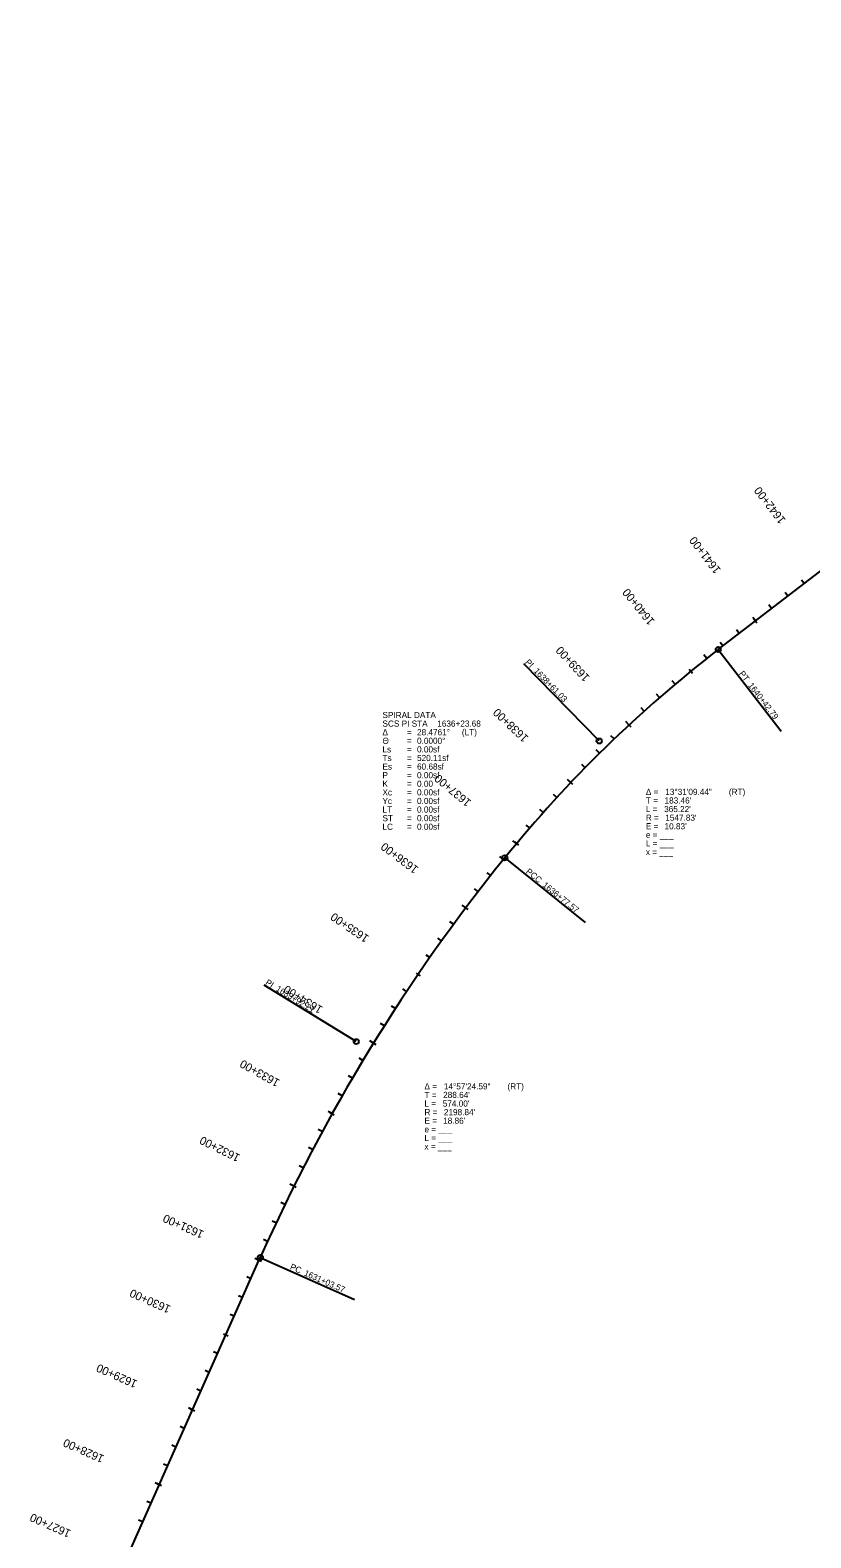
# Model space of a CAD drawing. Extents: x 14119411 to 14122090, y 8669365 to 8673150.
# Drawn here: x 14120185 to 14121138, y 8671257 to 8673099 of the extents above; entities that cross this region are included whole.
import ezdxf

# ---------------------------------------------------------------- set-up
doc = ezdxf.new("R2010")
doc.units = 0
for name, color, linetype in [('Alignment', 7, 'Continuous'), ('Default', 7, 'Continuous'), ('TextAlignment', 7, 'Continuous'), ('TextAlignmentLrg', 7, 'Continuous'), ('TextAlignmentSml', 7, 'Continuous')]:
    doc.layers.add(name, color=color, linetype=linetype)

msp = doc.modelspace()

# ---------------------------------------------------------------- linework, layer by layer
at = {"layer": 'Alignment'}
for p, q in [((14121025, 8672342.6), (14122009.4, 8673099.3)), ((14120263.5, 8671145.2), (14120465.7, 8671599.8))]:
    msp.add_line(p, q, dxfattribs=at)
for centre, radius, start, end in [((14121968.4, 8671115.4), 1547.8, 127.5512, 141.0704), ((14122474.8, 8670706.4), 2198.8, 141.0704, 156.0273)]:
    msp.add_arc(centre, radius, start, end, dxfattribs=at)
at = {"layer": 'Default'}
for p, q in [((14121025, 8672342.6), (14122009.4, 8673099.3)), ((14120263.5, 8671145.2), (14120465.7, 8671599.8))]:
    msp.add_line(p, q, dxfattribs=at)
for centre, radius, start, end in [((14121968.4, 8671115.4), 1547.8, 127.5512, 141.0704), ((14122474.8, 8670706.4), 2198.8, 141.0704, 156.0273)]:
    msp.add_arc(centre, radius, start, end, dxfattribs=at)
at = {"layer": 'TextAlignment'}
for p, q in [((14121025, 8672342.6), (14121101.8, 8672242.7)), ((14120879.6, 8672230.8), (14120787.4, 8672325.2)), ((14120787.4, 8672325.2), (14120787.4, 8672325.2)), ((14121101.8, 8672242.7), (14121101.8, 8672242.7)), ((14120764.3, 8672088), (14120862.3, 8672008.9)), ((14120764.3, 8672088), (14120862.3, 8672008.9)), ((14120862.3, 8672008.9), (14120862.3, 8672008.9)), ((14120862.3, 8672008.9), (14120862.3, 8672008.9)), ((14120582.9, 8671863.5), (14120470.3, 8671932.4)), ((14120470.3, 8671932.4), (14120470.3, 8671932.4)), ((14120465.7, 8671599.8), (14120580.8, 8671548.6)), ((14120580.8, 8671548.6), (14120580.8, 8671548.6))]:
    msp.add_line(p, q, dxfattribs=at)
for centre in [(14121025, 8672342.6), (14120879.6, 8672230.8), (14120764.3, 8672088), (14120764.3, 8672088), (14120582.9, 8671863.5), (14120465.7, 8671599.8)]:
    msp.add_circle(centre, 3.12, dxfattribs=at)
at = {"layer": 'TextAlignmentLrg'}
for p, q in [((14121070.4, 8672377.5), (14121067.1, 8672381.8)), ((14120989.5, 8672318.4), (14120993.4, 8672313.7)), ((14120916, 8672250.5), (14120912.3, 8672254.5)), ((14120844.9, 8672180.2), (14120841, 8672183.9)), ((14120778.5, 8672105.4), (14120774.3, 8672108.9)), ((14120716.6, 8672026.9), (14120712.3, 8672030.1)), ((14120655.9, 8671947.3), (14120660.9, 8671943.8)), ((14120604, 8671861.7), (14120599.3, 8671864.6)), ((14120553.4, 8671775.5), (14120548.6, 8671778.1)), ((14120506.8, 8671687), (14120501.9, 8671689.4)), ((14120464.2, 8671596.5), (14120459.2, 8671598.7)), ((14120420.8, 8671506.4), (14120426.4, 8671503.9)), ((14120382.9, 8671413.8), (14120378, 8671416)), ((14120342.3, 8671322.4), (14120337.3, 8671324.6))]:
    msp.add_line(p, q, dxfattribs=at)
at = {"layer": 'TextAlignmentSml'}
for p, q in [((14121129.9, 8672423.2), (14121126.5, 8672427.5)), ((14121110, 8672407.9), (14121106.7, 8672412.3)), ((14121090.2, 8672392.7), (14121086.9, 8672397)), ((14121068.5, 8672379.9), (14121072.3, 8672375)), ((14121050.6, 8672362.2), (14121047.2, 8672366.5)), ((14121011, 8672331.7), (14121007.6, 8672335.9)), ((14121030.7, 8672347), (14121027.4, 8672351.3)), ((14120989.5, 8672318.4), (14120993.4, 8672313.7)), ((14120972.2, 8672300.1), (14120968.7, 8672304.3)), ((14120953.2, 8672283.9), (14120949.6, 8672288)), ((14120934.5, 8672267.3), (14120930.8, 8672271.4)), ((14120913.9, 8672252.7), (14120918.1, 8672248.2)), ((14120897.8, 8672233.3), (14120894, 8672237.3)), ((14120879.9, 8672215.9), (14120876.1, 8672219.8)), ((14120862.3, 8672198.2), (14120858.4, 8672202)), ((14120842.7, 8672182.3), (14120847.1, 8672178)), ((14120827.9, 8672161.9), (14120823.8, 8672165.6)), ((14120811.1, 8672143.3), (14120807, 8672146.9)), ((14120794.7, 8672124.5), (14120790.5, 8672128)), ((14120776.2, 8672107.4), (14120780.9, 8672103.4)), ((14120762.7, 8672086), (14120758.4, 8672089.5)), ((14120747.1, 8672066.5), (14120742.8, 8672069.9)), ((14120731.8, 8672046.8), (14120727.4, 8672050.1)), ((14120714.2, 8672028.7), (14120719.1, 8672025)), ((14120701.7, 8672006.8), (14120697.3, 8672010)), ((14120687.1, 8671986.5), (14120682.6, 8671989.7)), ((14120672.6, 8671966.1), (14120668.1, 8671969.3)), ((14120655.9, 8671947.3), (14120660.9, 8671943.8)), ((14120644.4, 8671924.8), (14120639.9, 8671927.9)), ((14120630.7, 8671903.9), (14120626.1, 8671906.9)), ((14120617.2, 8671882.9), (14120612.6, 8671885.8)), ((14120601.4, 8671863.3), (14120606.6, 8671860.1)), ((14120590.9, 8671840.4), (14120586.3, 8671843.2)), ((14120578.2, 8671818.9), (14120573.5, 8671821.6)), ((14120565.6, 8671797.2), (14120560.9, 8671799.9)), ((14120550.7, 8671776.9), (14120556, 8671774)), ((14120541.3, 8671753.5), (14120536.5, 8671756.1)), ((14120529.6, 8671731.5), (14120524.7, 8671734)), ((14120518, 8671709.3), (14120513.2, 8671711.8)), ((14120504, 8671688.4), (14120509.5, 8671685.6)), ((14120495.7, 8671664.6), (14120490.8, 8671666.9)), ((14120485, 8671642), (14120480, 8671644.3)), ((14120474.5, 8671619.3), (14120469.5, 8671621.6)), ((14120461.4, 8671597.7), (14120467, 8671595.3)), ((14120454, 8671573.7), (14120449.1, 8671575.9)), ((14120443.9, 8671550.8), (14120438.9, 8671553)), ((14120433.7, 8671528), (14120428.7, 8671530.2)), ((14120420.8, 8671506.4), (14120426.4, 8671503.9)), ((14120413.4, 8671482.3), (14120408.4, 8671484.5)), ((14120403.3, 8671459.4), (14120398.3, 8671461.7)), ((14120393.1, 8671436.6), (14120388.1, 8671438.8)), ((14120380.1, 8671415), (14120385.7, 8671412.5)), ((14120372.8, 8671390.9), (14120367.8, 8671393.1)), ((14120362.6, 8671368.1), (14120357.6, 8671370.3)), ((14120352.5, 8671345.2), (14120347.5, 8671347.4)), ((14120339.5, 8671323.6), (14120345.1, 8671321.1)), ((14120332.2, 8671299.5), (14120327.2, 8671301.8)), ((14120322, 8671276.7), (14120317, 8671278.9))]:
    msp.add_line(p, q, dxfattribs=at)

# ---------------------------------------------------------------- texts
at = {"layer": 'TextAlignment'}
for s, rotation, p in [('PI ', 314.3108, (14120788.5, 8672326.4)), ('1638+61.03', 314.3108, (14120799, 8672315.7)), ('PT', 307.5512, (14121049.9, 8672312.9)), ('1640+42.79', 307.5512, (14121061, 8672298.5)), ('PCC', 321.0704, (14120789.3, 8672070)), ('PCC', 321.0704, (14120789.3, 8672070)), ('1636+77.57', 321.0704, (14120809.7, 8672053.5)), ('1636+77.57', 321.0704, (14120809.7, 8672053.5)), ('PI ', 328.5489, (14120471.2, 8671933.8)), ('1633+92.21', 328.5489, (14120483.9, 8671926)), ('PC', 336.0273, (14120501.3, 8671585.7)), ('1631+03.57', 336.0273, (14120518.4, 8671578.1))]:
    msp.add_text(s, height=7.5, rotation=rotation, dxfattribs=at).set_placement(p)
for s, p in [('SPIRAL DATA', (14120614.9, 8672258.8)), ('Δ', (14120614.9, 8672237.8)), ('SCS PI STA ', (14120614.9, 8672248.3)), ('= ', (14120644.9, 8672237.8)), ('28.4761°', (14120657.1, 8672237.8)), ('1636+23.68', (14120681.8, 8672248.3)), (' (LT)', (14120709.1, 8672237.8)), ('Θ ', (14120614.9, 8672227.3)), ('Ls', (14120614.9, 8672216.8)), ('= ', (14120644.9, 8672227.3)), ('0.0000°', (14120657.1, 8672227.3)), ('0.00sf', (14120657.1, 8672216.8)), ('Ts', (14120614.9, 8672206.3)), ('= ', (14120644.9, 8672216.8)), ('= ', (14120644.9, 8672206.3)), ('520.11sf', (14120657.1, 8672206.3)), ('Es', (14120614.9, 8672195.8)), ('P', (14120614.9, 8672185.3)), ('= ', (14120644.9, 8672195.8)), ('= ', (14120644.9, 8672185.3)), ('0.00sf', (14120657.1, 8672185.3)), ('60.68sf', (14120657.1, 8672195.8)), ('Xc', (14120614.9, 8672164.3)), ('K', (14120614.9, 8672174.8)), ('= ', (14120644.9, 8672174.8)), ('= ', (14120644.9, 8672164.3)), ('0.00', (14120657.1, 8672174.8)), ('0.00sf', (14120657.1, 8672164.3)), ('Δ = ', (14120936.6, 8672164.9)), ('13°31\'09.44"', (14120960.3, 8672164.9)), (' (RT)', (14121035.2, 8672164.9)), ('Yc', (14120614.9, 8672153.8)), ('LT', (14120614.9, 8672143.3)), ('= ', (14120644.9, 8672153.8)), ('0.00sf', (14120657.1, 8672153.8)), ('0.00sf', (14120657.1, 8672143.3)), ('T = ', (14120936.6, 8672154.4)), ('L = ', (14120936.6, 8672143.9)), ("365.22'", (14120958.9, 8672143.9)), ("183.46'", (14120959.4, 8672154.4)), ('ST ', (14120614.9, 8672132.8)), ('= ', (14120644.9, 8672143.3)), ('= ', (14120644.9, 8672132.8)), ('0.00sf', (14120657.1, 8672132.8)), ('R = ', (14120936.6, 8672133.4)), ("10.83'", (14120959.4, 8672122.9)), ("1547.83'", (14120960.3, 8672133.4)), ('LC', (14120614.9, 8672122.3)), ('= ', (14120644.9, 8672122.3)), ('0.00sf', (14120657.1, 8672122.3)), ('e = ___ ', (14120936.6, 8672112.4)), ('E = ', (14120936.6, 8672122.9)), ('x = ___', (14120936.6, 8672091.4)), ('L = ___', (14120936.6, 8672101.9)), ('T = ', (14120666.2, 8671794.6)), ('Δ = ', (14120666.2, 8671805.1)), ("288.64'", (14120689, 8671794.6)), ('14°57\'24.59"', (14120689.9, 8671805.1)), (' (RT)', (14120764.8, 8671805.1)), ('L = ', (14120666.2, 8671784.1)), ('R = ', (14120666.2, 8671773.6)), ("574.00'", (14120688.5, 8671784.1)), ("2198.84'", (14120689.9, 8671773.6)), ('E = ', (14120666.2, 8671763.1)), ("18.86'", (14120689, 8671763.1)), ('e = ___ ', (14120666.2, 8671752.6)), ('L = ___', (14120666.2, 8671742.1)), ('x = ___', (14120666.2, 8671731.6))]:
    msp.add_text(s, height=7.5, dxfattribs=at).set_placement(p)
at = {"layer": 'TextAlignmentLrg'}
for s, rotation, p in [('1640+00', 129.1349, (14120948, 8672377.4)), ('1635+00', 145.6973, (14120599.3, 8671992)), ('1630+00', 156.0273, (14120357.1, 8671540.2))]:
    msp.add_text(s, height=10.02, rotation=rotation, dxfattribs=at).set_placement(p)
at = {"layer": 'TextAlignmentSml'}
for s, rotation, p in [('1642+00', 127.5512, (14121107.9, 8672500.9)), ('1641+00', 127.5512, (14121028.7, 8672440)), ('1640+00', 129.1349, (14120948, 8672377.4)), ('1639+00', 132.8366, (14120868.7, 8672308.9)), ('1638+00', 136.5383, (14120793.9, 8672235.4)), ('1637+00', 140.24, (14120724.1, 8672157.2)), ('1636+00', 143.0916, (14120659.7, 8672075.9)), ('1635+00', 145.6973, (14120599.3, 8671992)), ('1634+00', 148.303, (14120542.8, 8671905.4)), ('1633+00', 150.9088, (14120490.3, 8671816.3)), ('1632+00', 153.5145, (14120441.9, 8671724.9)), ('1631+00', 156.0273, (14120397.7, 8671631.6)), ('1630+00', 156.0273, (14120357.1, 8671540.2)), ('1629+00', 156.0273, (14120316.4, 8671448.8)), ('1628+00', 156.0273, (14120275.8, 8671357.4)), ('1627+00', 156.0273, (14120235.2, 8671266.1))]:
    msp.add_text(s, height=10.02, rotation=rotation, dxfattribs=at).set_placement(p)

doc.saveas('drawing.dxf')
